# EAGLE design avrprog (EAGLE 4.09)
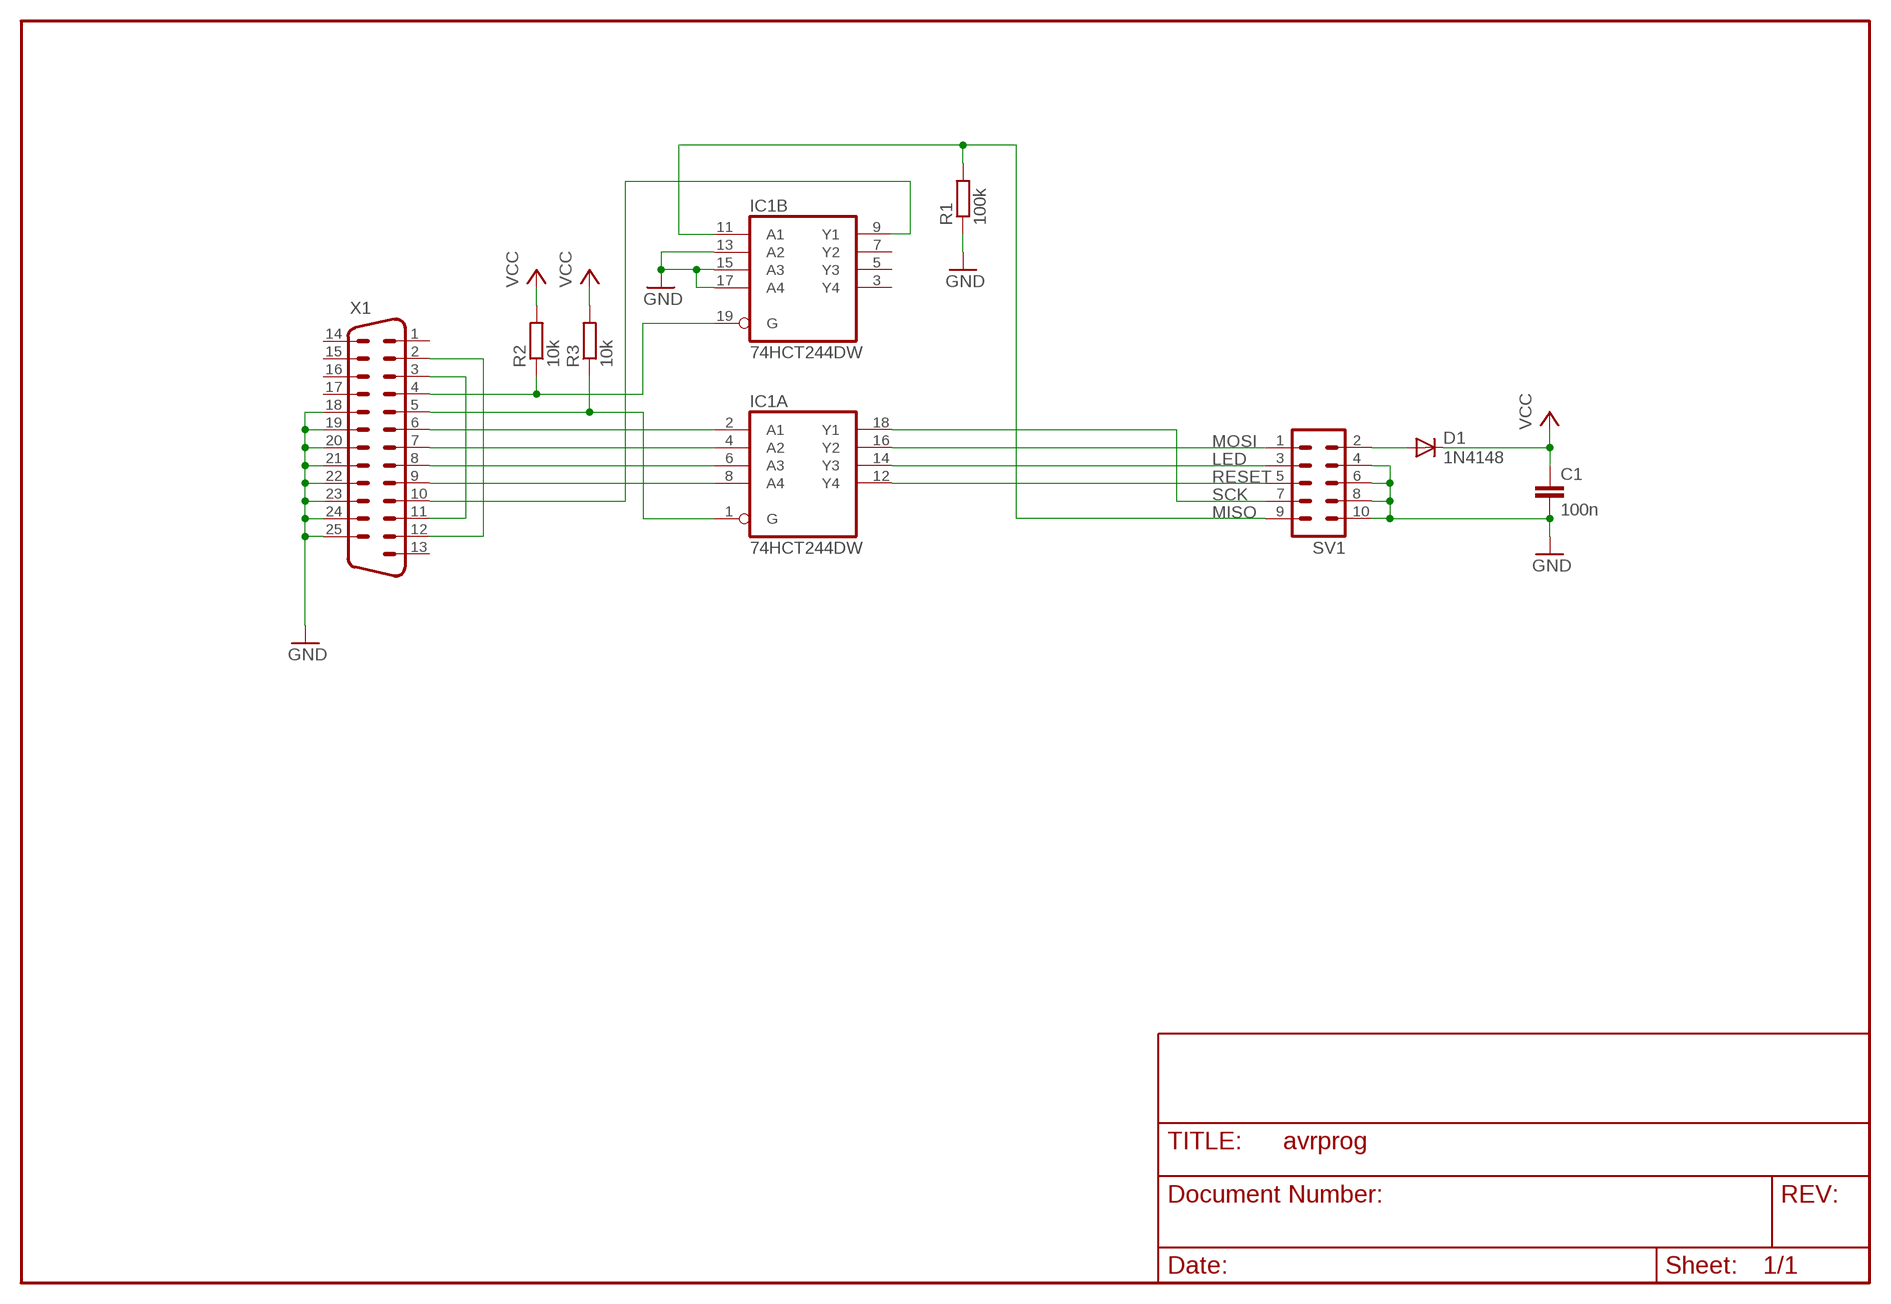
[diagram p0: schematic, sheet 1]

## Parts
C1  100n  C-EU025-024X044  [C025-024X044]
D1  1N4148  [DO35-10]
IC1  74HCT244DW  [SO20W]
R1  100k  R-EU_M1206  [M1206]
R2  10k  R-EU_M1206  [M1206]
R3  10k  R-EU_M1206  [M1206]
SV1  MA05-2  [MA05-2]
X1  M25D  [M25D]

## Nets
GND: C1.2 IC1.13(B:A2) IC1.15(B:A3) IC1.17(B:A4) R1.1 SV1.4 SV1.6 SV1.8 SV1.10 X1.18 X1.19 X1.20 X1.21 X1.22 X1.23 X1.24 X1.25
LED: IC1.14(A:Y3) SV1.3
MISO: IC1.11(B:A1) R1.2 SV1.9
MOSI: IC1.16(A:Y2) SV1.1
N$1: D1.A SV1.2
N$3: IC1.1(A:G) R3.1 X1.5
N$4: IC1.19(B:G) R2.1 X1.4
N$5: IC1.2(A:A1) X1.6
N$6: IC1.4(A:A2) X1.7
N$7: IC1.6(A:A3) X1.8
N$8: IC1.8(A:A4) X1.9
N$9: IC1.9(B:Y1) X1.10
N$18: X1.3 X1.11
N$19: X1.2 X1.12
RESET: IC1.12(A:Y4) SV1.5
SCK: IC1.18(A:Y1) SV1.7
VCC: C1.1 D1.C R2.2 R3.2
Unconnected: IC1.3(B:Y4) IC1.5(B:Y3) IC1.7(B:Y2) X1.1 X1.13 X1.14 X1.15 X1.16 X1.17

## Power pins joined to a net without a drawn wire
GND: IC1.10(P:GND)
VCC: IC1.20(P:VCC)

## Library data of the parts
C1 = rcl:C-EU: CAPACITOR, European symbol
D1 = diode:1N4148: DIODE
IC1 = 74xx-eu:74*244: Octal BUFFER and LINE DRIVER, 3-state
R1-R3 = rcl:R-EU_: RESISTOR, European symbol
SV1 = con-lstb:MA05-2: PIN HEADER
X1 = _bu-subd:M25: SUB-D

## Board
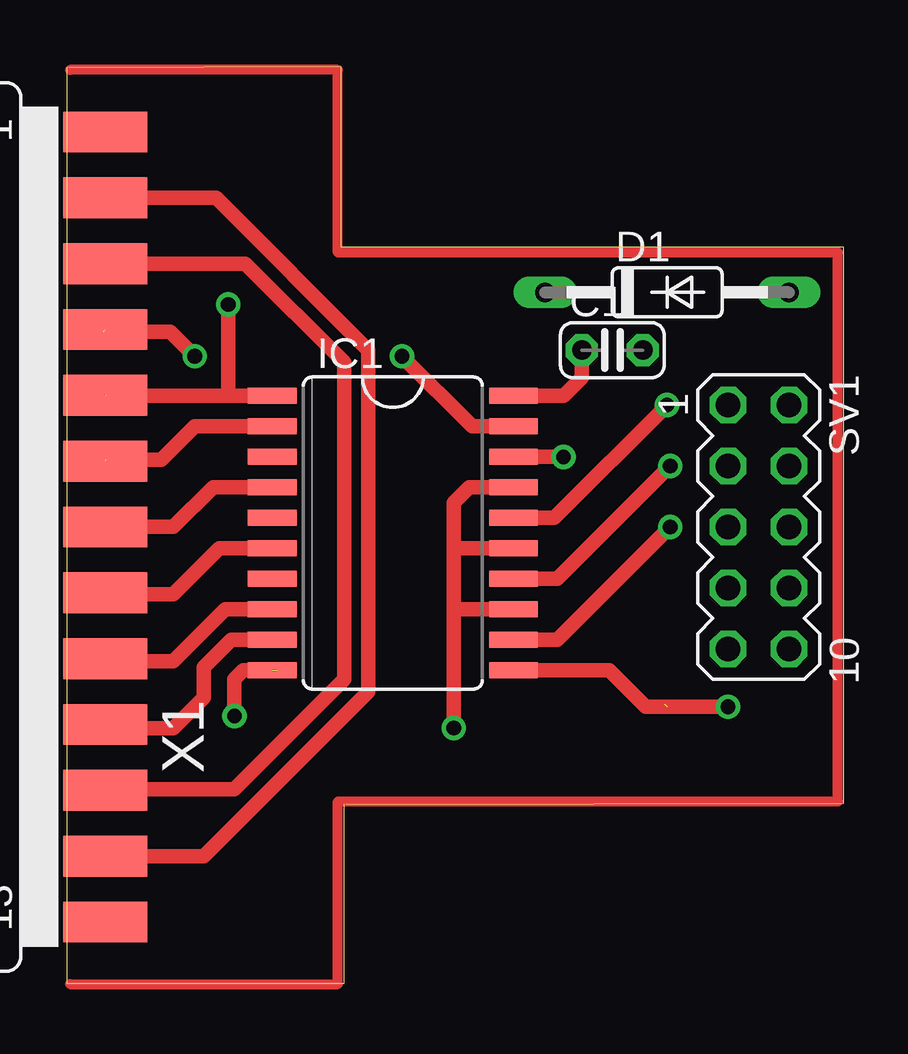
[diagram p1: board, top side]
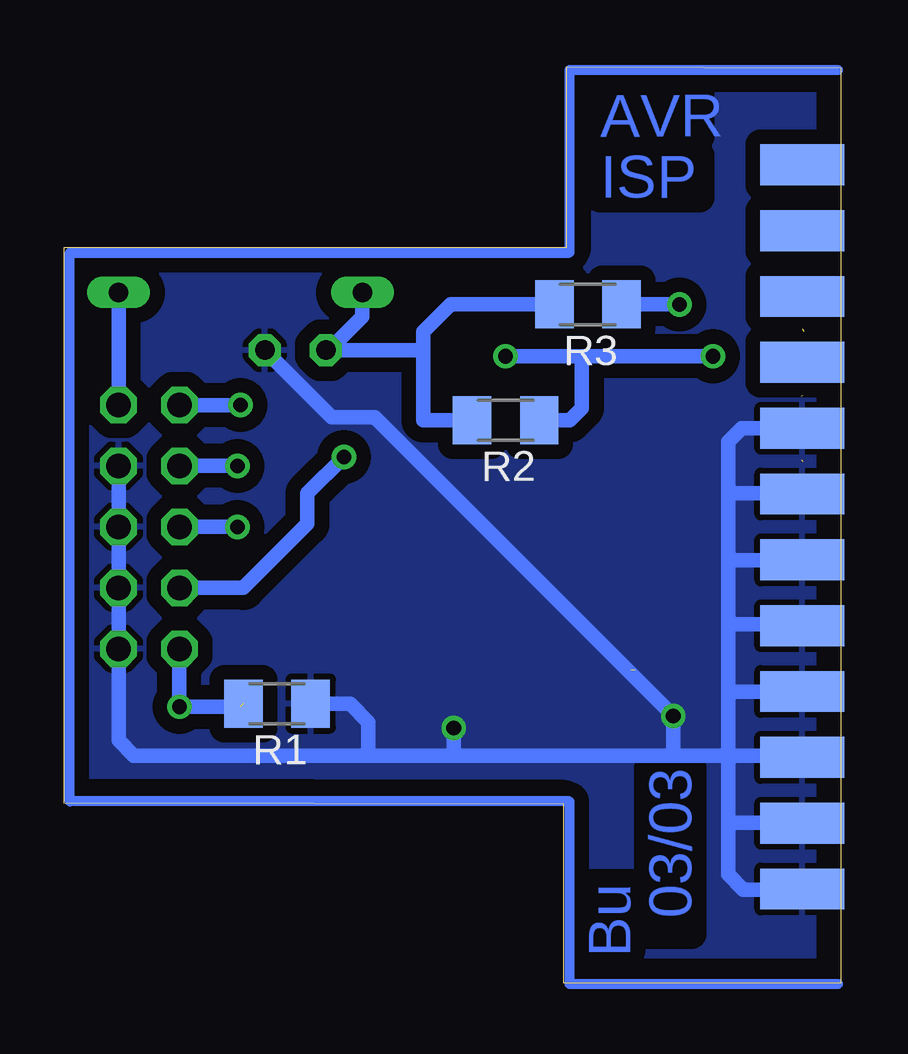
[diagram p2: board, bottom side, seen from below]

Size 32.37 x 38.19 mm. Coordinates in mm from the lower left corner, seen from the top.
Outline: 0,0 11.55,0 11.55,7.46 32.37,7.49 32.37,30.66 11.43,30.66 11.43,38.19 0,38.15 0,0
Copper layers used: Top, Bottom

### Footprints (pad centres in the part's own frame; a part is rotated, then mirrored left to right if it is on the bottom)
C025-024X044 = drill 0.813 octagon: 1 -1.27,0; 2 1.27,0
DO35-10 = drill 0.813 long: A 5.08,0; C -5.08,0
SO20W = smd 0.66 x 2.032: 1 -5.715,-5.029; 2 -4.445,-5.029; 3 -3.175,-5.029; 4 -1.905,-5.029; 5 -0.635,-5.029; 6 0.635,-5.029; 7 1.905,-5.029; 8 3.175,-5.029; 9 4.445,-5.029; 10 5.715,-5.029; 11 5.715,5.029; 12 4.445,5.029; 13 3.175,5.029; 14 1.905,5.029; 15 0.635,5.029; 16 -0.635,5.029; 17 -1.905,5.029; 18 -3.175,5.029; 19 -4.445,5.029; 20 -5.715,5.029
M1206 = smd 1.6 x 2: 1 -1.4,0; 2 1.4,0
MA05-2 = drill 1.016 octagon: 1 -5.08,-1.27; 2 -5.08,1.27; 3 -2.54,-1.27; 4 -2.54,1.27; 5 0,-1.27; 6 0,1.27; 7 2.54,-1.27; 8 2.54,1.27; 9 5.08,-1.27; 10 5.08,1.27
M25D = smd 1.7 x 3.5: 1 16.459,-6.045; 2 13.716,-6.045; 3 10.973,-6.045; 4 8.23,-6.045; 5 5.486,-6.045; 6 2.743,-6.045; 7 0,-6.045; 8 -2.743,-6.045; 9 -5.486,-6.045; 10 -8.23,-6.045; 11 -10.973,-6.045; 12 -13.716,-6.045; 13 -16.459,-6.045 | smd 1.7 x 3.5 bottom: 14 15.088,-6.045; 15 12.344,-6.045; 16 9.601,-6.045; 17 6.858,-6.045; 18 4.115,-6.045; 19 1.372,-6.045; 20 -1.372,-6.045; 21 -4.115,-6.045; 22 -6.858,-6.045; 23 -9.601,-6.045; 24 -12.344,-6.045; 25 -15.088,-6.045

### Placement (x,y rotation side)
C1  22.73,26.38 0 top
D1  25.01,28.79 0 top
IC1  13.58,18.76 270 top
R1  23.49,11.65 180 bottom
R2  13.97,23.46 180 bottom
R3  10.54,28.28 180 bottom
SV1  28.82,19.01 270 top
X1  -4.45,19.01 90 top

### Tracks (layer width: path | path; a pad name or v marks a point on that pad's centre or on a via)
GND  (via drill 0.61)  (1 unrouted)
  Top 0.61: v6.98,11.14 6.98,12.66 7.36,13.04 8.76,13.04 | 16.12,15.58 IC1.13 | 16.12,15.58 16.12,18.12 | 16.12,18.12 16.12,20.03 16.76,20.66 IC1.17 | 16.12,18.12 IC1.15 | v16.12,10.63 16.12,15.58
  Bottom 0.61: X1.18 4.13,23.13 4.69,22.57 4.69,20.41 | 4.69,17.61 4.69,20.41 | 4.69,14.95 4.69,17.61 | 4.69,12.15 4.69,14.95 | 4.69,9.49 4.69,12.15 | 4.69,6.69 4.69,9.49 | 4.69,6.69 4.69,4.53 4.06,3.9 1.65,3.9 | 4.69,6.69 2.66,6.69 | 4.69,9.49 4.57,9.49 | 4.57,9.49 2.54,9.49 | 4.69,12.15 2.54,12.15 | 4.69,14.95 2.41,14.95 | 4.69,17.61 2.03,17.61 | 4.69,20.41 2.28,20.41 | 4.57,9.49 6.98,9.49 | 6.98,9.49 16.12,9.49 | 19.81,9.49 16.25,9.49 16.12,9.49 | 19.81,9.49 29.46,9.49 30.09,10.12 SV1.4 | 6.98,9.49 v6.98,11.14 19.43,23.58 21.2,23.58 C1.2 | R1.1 20.44,11.65 19.68,10.88 19.68,9.61 19.81,9.49 | 16.12,9.49 v16.12,10.63
  pour Bottom (isolate 0.61): 0.12,38.19 0.12,0.09 11.04,0.09 11.17,0.22 11.17,7.46 11.43,7.71 32,7.71 32.13,7.58 32.13,30.44 11.43,30.44 11.43,38.06 11.3,38.06
LED  (via drill 0.61)
  Top 0.61: IC1.14 20.44,16.85 v25.14,21.55
  Bottom 0.61: v25.14,21.55 SV1.3
MISO  (via drill 0.61)  (1 unrouted)
  Top 0.61: IC1.11 22.6,13.04 24.12,11.52 v27.55,11.52
  Bottom 0.61: SV1.9 v27.55,11.52 25.01,11.52
MOSI  (via drill 0.61)
  Top 0.61: IC1.16 20.31,19.39 v25.01,24.09
  Bottom 0.61: v25.01,24.09 SV1.1
N$1
  Bottom 0.61: SV1.2 D1.A
N$2
  Top 0.406: 0.12,38.06 11.3,38.06 11.3,30.44 32.13,30.44 32.13,7.58 11.3,7.58 11.3,-0.04 0.12,-0.04
N$3  (via drill 0.61)  (1 unrouted)
  Top 0.61: 6.73,24.47 IC1.1 | 1.65,24.47 6.73,24.47 | 6.73,24.47 v6.73,28.28
  Bottom 0.61: v6.73,28.28 R3.1
N$4  (via drill 0.61)  (1 unrouted)
  Top 0.61: IC1.19 16.89,23.2 v13.97,26.12 | v5.33,26.12 4.31,27.14 1.52,27.14
  Bottom 0.61: v5.33,26.12 10.79,26.12 | 10.79,26.12 v13.97,26.12 | R2.1 11.3,23.46 10.79,23.96 10.79,26.12
N$5  (1 unrouted)
  Top 0.61: IC1.2 5.33,23.2 3.93,21.81 1.65,21.81
N$6
  Top 0.61: IC1.4 6.09,20.66 4.44,19.01 X1.7
N$7
  Top 0.61: IC1.6 6.34,18.12 4.44,16.22 1.9,16.22 1.85,16.27 X1.8
N$8
  Top 0.61: IC1.8 6.6,15.58 4.44,13.42 1.9,13.42 1.8,13.53 X1.9
N$9
  Top 0.61: IC1.9 6.85,14.31 5.71,13.17 5.71,11.9 4.44,10.63 1.65,10.63 1.59,10.68 X1.10
N$18
  Top 0.61: X1.3 7.44,29.98 11.55,25.87 11.55,12.66 6.98,8.09 1.65,8.09 X1.11 | X1.11
N$19
  Top 0.61: X1.12 5.71,5.3 12.57,12.15 12.57,26.38 6.22,32.73 X1.2
N$21
  Bottom 0.406: 0.12,38.06 11.3,38.06 11.3,30.44 32.13,30.44 32.13,7.58 11.3,7.58 11.3,-0.04 0.12,-0.04
RESET  (via drill 0.61)
  Top 0.61: IC1.12 20.44,14.31 v25.14,19.01
  Bottom 0.61: v25.14,19.01 SV1.5
SCK  (via drill 0.61)
  Top 0.61: IC1.18 v20.7,21.93
  Bottom 0.61: v20.7,21.93 22.22,20.41 22.22,19.14 24.89,16.47 SV1.7
VCC
  Top 0.61: IC1.20 20.7,24.47 21.46,25.23 C1.1
  Bottom 0.61: R2.2 17.39,23.46 17.39,26.38 | 17.39,26.38 C1.1 21.33,26.38 19.93,27.77 D1.C | R3.2 16.25,28.28 17.39,27.14 17.39,26.38

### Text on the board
Bottom: AVR | ISP | 03/03 | Bu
